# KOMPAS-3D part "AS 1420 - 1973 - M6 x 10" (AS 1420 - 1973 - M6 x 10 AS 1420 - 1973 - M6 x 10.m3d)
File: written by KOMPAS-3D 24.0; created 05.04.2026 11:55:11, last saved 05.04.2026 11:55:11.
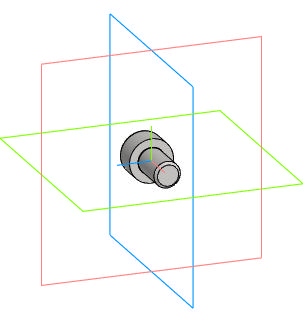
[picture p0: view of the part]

Document properties: Автор: R2D2; Полное имя файла: E:\Работа\Зайцев\Аксессуары для пневмоприводов\Ручной дублер DN.ru\MON4-1200-T54-ISO Ручной дублер DN.ru\исходные материалы\AS 1420 - 1973 - M6 x 10 AS 1420 - 1973 - M6 x 10.m3d

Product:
- Body: Solid1  | qty 1
- Part/product: AS 1420 - 1973 - M6 x 10
    Комментарий: Винты с шестигранным   углублением метрические   ISO
    additional columns: Сталь, мягкая

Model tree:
1. Solid1  (labels: Solid1)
